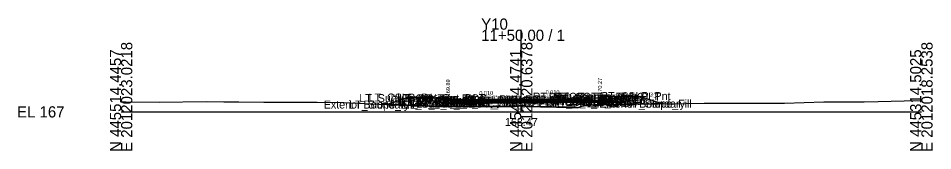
# Model space of a CAD drawing. Extents: x -26 to 203, y -10 to 3517.
# Drawn here: x -25.7 to 202.8, y 2990.3 to 3023.4 of the extents above; entities that cross this region are included whole.
import ezdxf

# ---------------------------------------------------------------- set-up
doc = ezdxf.new("R2010")
doc.units = 0
for name, color, linetype in [('Default', 7, 'Continuous'), ('Exist Cross Section Cell', 7, 'Continuous'), ('Exist XS Center Line Elevation Label', 7, 'Continuous'), ('Exist XS Ground Line', 7, 'Continuous'), ('Prop CMT Conc Surface', 7, 'Continuous'), ('Prop CMT Concrete Structures', 7, 'Continuous'), ('Prop CMT Pvmt Course 1', 7, 'Continuous'), ('Prop CMT Pvmt Course 1 CG', 7, 'Continuous'), ('Prop CMT Pvmt Course 2', 7, 'Continuous'), ('Prop CMT Pvmt Course 3', 7, 'Continuous'), ('Prop CMT Pvmt Surface', 7, 'Continuous'), ('Prop CMT Slope Grass', 7, 'Continuous'), ('Prop CMT Subgrade Earthwork', 7, 'Continuous'), ('Prop XS Earthwork Shape', 7, 'Continuous'), ('Prop XS Hydro Elevations', 7, 'Continuous'), ('Prop XS SE Text', 7, 'Continuous'), ('Prop XS Side Slope Text', 7, 'Continuous'), ('Scratch_Level_0', 7, 'Continuous')]:
    doc.layers.add(name, color=color, linetype=linetype)

msp = doc.modelspace()

# ---------------------------------------------------------------- linework, layer by layer
at = {"layer": 'Exist Cross Section Cell'}
for p, q in [((100, 3000), (100, 3020.53)), ((0, 3000), (100, 3000)), ((100, 3000), (200, 3000))]:
    msp.add_line(p, q, dxfattribs=at)
at = {"layer": 'Exist XS Ground Line'}
msp.add_lwpolyline([(0, 3002.49), (1.15, 3002.49), (9.55, 3002.47), (21.26, 3002.56), (25.64, 3002.52), (29.45, 3002.49), (35.65, 3002.43), (39.22, 3002.44), (45.65, 3002.41), (48.99, 3002.4), (55.65, 3002.37), (62.64, 3002.04), (66.36, 3001.85), (69.27, 3001.76), (79.87, 3001.32), (82.21, 3001.29), (86.9, 3001.31), (88.78, 3001.32), (92.93, 3001.35), (97.78, 3001.31), (98.51, 3001.34), (99.07, 3001.43), (100.24, 3001.48), (101.65, 3001.36), (101.95, 3001.33), (104.78, 3001.3), (108.85, 3001.22), (111.4, 3001.19), (112.65, 3001.1), (114.03, 3001.05), (115.22, 3001.4), (116.71, 3001.65), (132.48, 3002.01), (134.51, 3002.04), (135.53, 3002.06), (136.49, 3002.05), (145.74, 3002.14), (155.25, 3002.22), (155.55, 3002.21), (165.32, 3002.21), (165.77, 3002.21), (175.61, 3002.52), (176.06, 3002.53), (185.75, 3002.5), (189.21, 3002.59), (195.71, 3002.74), (200, 3002.87)], dxfattribs=at)
at = {"layer": 'Prop CMT Conc Surface'}
for points in [[(81.69, 3002.89), (81.69, 3003.39), (81.19, 3003.39)], [(83.69, 3002.99), (81.69, 3002.89)], [(117.66, 3003.33), (119.66, 3003.27)], [(119.66, 3003.27), (119.66, 3003.77), (120.16, 3003.77)]]:
    msp.add_lwpolyline(points, dxfattribs=at)
at = {"layer": 'Prop CMT Concrete Structures'}
for points in [[(83.69, 3002.99), (81.69, 3002.89), (81.69, 3003.39), (81.19, 3003.39)], [(81.19, 3003.39), (81.19, 3002.38), (83.69, 3002.4)], [(83.69, 3002.4), (83.69, 3002.99)], [(117.66, 3003.33), (119.66, 3003.27), (119.66, 3003.77), (120.16, 3003.77)], [(120.16, 3003.77), (120.16, 3002.77), (117.66, 3002.74)], [(117.66, 3002.74), (117.66, 3003.33)]]:
    msp.add_lwpolyline(points, dxfattribs=at)
at = {"layer": 'Prop CMT Pvmt Course 1'}
for points in [[(100, 3003.15), (83.69, 3002.99)], [(83.69, 3002.99), (83.69, 3002.74)], [(100, 3003.15), (117.66, 3003.33)], [(100, 3002.9), (100, 3003.15)], [(100, 3002.9), (100, 3003.15)], [(117.66, 3003.08), (100, 3002.9)], [(117.66, 3003.33), (117.66, 3003.08)], [(83.69, 3002.74), (100, 3002.9)]]:
    msp.add_lwpolyline(points, dxfattribs=at)
msp.add_lwpolyline([(100, 3002.9), (100, 3003.02), (100, 3003.02), (100, 3002.9)], close=True, dxfattribs=at)
msp.add_lwpolyline([(100, 3002.9), (100, 3003.02), (100, 3003.02), (100, 3002.9)], close=True, dxfattribs=at)
at = {"layer": 'Prop CMT Pvmt Course 1 CG'}
for points in [[(83.69, 3002.4), (80.69, 3002.37), (80.35, 3002.04)], [(80.35, 3002.04), (83.69, 3002.07)], [(83.69, 3002.07), (83.69, 3002.4)], [(117.66, 3002.74), (120.66, 3002.77), (120.99, 3002.44)], [(117.66, 3002.41), (117.66, 3002.74)], [(120.99, 3002.44), (117.66, 3002.41)]]:
    msp.add_lwpolyline(points, dxfattribs=at)
at = {"layer": 'Prop CMT Pvmt Course 2'}
for points in [[(100, 3002.9), (117.66, 3003.08)], [(117.66, 3003.08), (117.66, 3002.74)], [(100, 3002.9), (83.69, 3002.74)], [(83.69, 3002.74), (83.69, 3002.4)], [(83.69, 3002.4), (100, 3002.57)], [(100, 3002.57), (100, 3002.9)], [(100, 3002.57), (100, 3002.9)], [(117.66, 3002.74), (100, 3002.57)]]:
    msp.add_lwpolyline(points, dxfattribs=at)
at = {"layer": 'Prop CMT Pvmt Course 3'}
for points in [[(100, 3002.57), (83.69, 3002.4)], [(83.69, 3002.4), (83.69, 3002.07)], [(83.69, 3002.07), (100, 3002.23)], [(100, 3002.57), (117.66, 3002.74)], [(100, 3002.23), (100, 3002.57)], [(100, 3002.23), (100, 3002.57)], [(117.66, 3002.41), (100, 3002.23)], [(117.66, 3002.74), (117.66, 3002.41)]]:
    msp.add_lwpolyline(points, dxfattribs=at)
at = {"layer": 'Prop CMT Pvmt Surface'}
for points in [[(100, 3003.15), (83.69, 3002.99)], [(100, 3003.15), (117.66, 3003.33)]]:
    msp.add_lwpolyline(points, dxfattribs=at)
at = {"layer": 'Prop CMT Slope Grass'}
for points in [[(81.19, 3003.39), (71.69, 3003.58), (66.49, 3001.84)], [(120.16, 3003.77), (129.66, 3003.96), (135.37, 3002.05)]]:
    msp.add_lwpolyline(points, dxfattribs=at)
at = {"layer": 'Prop CMT Subgrade Earthwork'}
for points in [[(83.69, 3002.07), (80.35, 3002.04), (78.96, 3003.43)], [(117.66, 3002.41), (120.99, 3002.44), (122.36, 3003.81)], [(100, 3002.23), (83.69, 3002.07)], [(100, 3002.23), (117.66, 3002.41)]]:
    msp.add_lwpolyline(points, dxfattribs=at)
at = {"layer": 'Prop XS Earthwork Shape'}
msp.add_lwpolyline([(100, 3002.23), (117.66, 3002.41), (120.99, 3002.44), (122.36, 3003.81), (129.66, 3003.96), (135.37, 3002.05), (134.51, 3002.04), (132.48, 3002.01), (116.71, 3001.65), (115.22, 3001.4), (114.03, 3001.05), (112.65, 3001.1), (111.4, 3001.19), (108.85, 3001.22), (104.78, 3001.3), (101.95, 3001.33), (101.65, 3001.36), (100.24, 3001.48), (99.07, 3001.43), (98.51, 3001.34), (97.78, 3001.31), (92.93, 3001.35), (88.78, 3001.32), (86.9, 3001.31), (82.21, 3001.29), (79.87, 3001.32), (69.27, 3001.76), (66.49, 3001.84), (71.69, 3003.58), (78.96, 3003.43), (80.35, 3002.04), (83.69, 3002.07)], close=True, dxfattribs=at)

# ---------------------------------------------------------------- texts
at = {"layer": 'Default'}
msp.add_text('-', height=0.0001, dxfattribs=at).set_placement((0, 3000))
at = {"layer": 'Exist Cross Section Cell'}
for s, p in [('Y10', (90, 3020.53)), ('11+50.00 / 1', (90, 3017.73)), ('EL 167', (-26, 2998.6))]:
    msp.add_text(s, height=2.8, dxfattribs=at).set_placement(p)
for s, p in [('E 2012023.0218', (2.8, 2990)), ('E 2012020.6378', (102.8, 2990)), ('E 2012018.2538', (202.8, 2990)), ('N 445514.4457', (0, 2990)), ('N 445414.4741', (100, 2990)), ('N 445314.5025', (200, 2990))]:
    msp.add_text(s, height=2.8, rotation=90, dxfattribs=at).set_placement(p)
at = {"layer": 'Exist XS Center Line Elevation Label'}
msp.add_text('168.47', height=2, dxfattribs=at).set_placement((95.94, 2996.47))
at = {"layer": 'Prop XS Hydro Elevations'}
for s, p in [('169.89', (82.19, 3003.89)), ('170.27', (120.16, 3004.27))]:
    msp.add_text(s, height=1, rotation=90, dxfattribs=at).set_placement(p)
at = {"layer": 'Prop XS SE Text'}
msp.add_text('0.010', height=1, rotation=1.1458, dxfattribs=at).set_placement((89.55, 3004.18))
msp.add_text('0.010', height=1, dxfattribs=at).set_placement((106.1, 3004.4))
at = {"layer": 'Prop XS Side Slope Text'}
for rotation, p in [(18.4332, (68.1, 3003.17)), (341.5668, (132, 3003.97))]:
    msp.add_text('3:1', height=1, rotation=rotation, dxfattribs=at).set_placement(p)
at = {"layer": 'Scratch_Level_0'}
for s, p in [('Exterior Boundary', (50.64, 3000.84)), ('LT_Slope_Fill', (57.01, 3000.84)), ('LT_Sub_Trench_Out_DLT', (59.53, 3002.43)), ('LT_CSLP_Pnt', (61.86, 3002.58)), ('LT_CG1_Shelf_Out', (67.24, 3001.37)), ('LT_CG_Top_Face', (68.95, 3002.39)), ('LT_CG_Top_BOC', (69.47, 3002.39)), ('LT_CG_Bot_BOC', (69.5, 3001.38)), ('LT_CG_Top_Gut', (69.93, 3001.89)), ('LT_Sub_OEOP', (70.46, 3001.04)), ('LT_CG_Bot_IE', (73.6, 3001.4)), ('LT_Sub_OEOT', (73.77, 3001.07)), ('LT_PV2_OEOT', (73.86, 3001.74)), ('LT_PV3_OEOT', (73.86, 3001.4)), ('LT_PV1_OEOT', (74.43, 3001.99)), ('RT_Sub_OEEOP', (89.17, 3001.23)), ('LT_Sub_OEEOP', (89.21, 3001.23)), ('RT_PV2_OEEOP', (89.26, 3001.9)), ('RT_PV3_OEEOP', (89.26, 3001.57)), ('LT_PV2_OEEOP', (89.31, 3001.9)), ('LT_PV3_OEEOP', (89.31, 3001.57)), ('RT_PV1_OEEOP', (89.83, 3002.02)), ('LT_PV1_OEEOP', (89.87, 3002.02)), ('RT_PV2_IEEOP', (89.91, 3001.9)), ('LT_PV2_IEEOP', (89.95, 3001.9)), ('RT_PV1_IEEOP', (90.47, 3002.02)), ('LT_PV1_IEEOP', (90.52, 3002.02)), ('PV2_PGL', (93.91, 3001.9)), ('PV1_PGL', (94.47, 3002.15)), ('RT_Sub_Trench_Out_DLT', (102.88, 3002.81)), ('RT_CG_Top_Face', (106.87, 3002.77)), ('RT_CG1_Shelf_Out', (107.16, 3001.77)), ('RT_CG_Bot_IE', (107.53, 3001.74)), ('RT_Sub_OEOT', (107.69, 3001.41)), ('RT_PV2_OEOT', (107.79, 3002.08)), ('RT_PV3_OEOT', (107.79, 3001.74)), ('RT_CG_Top_Gut', (107.85, 3002.27)), ('RT_PV1_OEOT', (108.35, 3002.33)), ('RT_CG_Top_BOC', (108.4, 3002.77)), ('RT_CG_Bot_BOC', (108.43, 3001.77)), ('RT_Sub_OEOP', (111.05, 3001.44)), ('Exterior Boundary', (119.51, 3001.05)), ('RT_CSLP_Pnt', (119.79, 3002.96)), ('RT_Slope_Fill', (125.84, 3001.05))]:
    msp.add_text(s, height=2, dxfattribs=at).set_placement(p)

doc.saveas('drawing.dxf')
